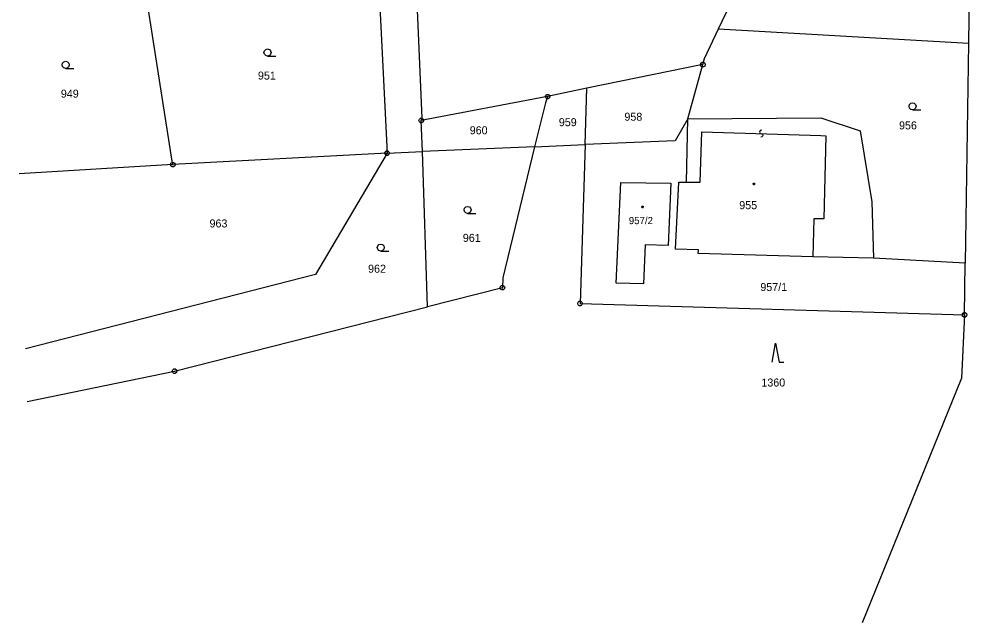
# Model space of a CAD drawing. Extents: x -456675 to -456278, y -1112395 to -1112217.
# Drawn here: x -456664.8 to -456563.6, y -1112392.8 to -1112328.7 of the extents above; entities that cross this region are included whole.
import ezdxf

# ---------------------------------------------------------------- set-up
doc = ezdxf.new("R2010")
doc.units = 0
doc.layers.add('Katastralni_mapa', color=7, linetype='Continuous')

msp = doc.modelspace()

# ---------------------------------------------------------------- linework, layer by layer
at = {"layer": 'Katastralni_mapa'}
for points in [[(-456590.54, -1112329.78), (-456578.75, -1112305.2)], [(-456563.64, -1112304.41), (-456564.02, -1112331.27)], [(-456627.45, -1112308.3), (-456625.73, -1112342.97)], [(-456648.52, -1112343.82), (-456653.24, -1112313.68)], [(-456622.01, -1112339.26), (-456622.84, -1112319.54)], [(-456592.04, -1112332.9), (-456590.54, -1112329.78)], [(-456590.54, -1112329.78), (-456564.02, -1112331.27)], [(-456564.02, -1112331.27), (-456564.35, -1112354.63)], [(-456638.41, -1112332.65), (-456638.6, -1112332.6), (-456638.74, -1112332.46), (-456638.79, -1112332.28), (-456638.74, -1112332.09), (-456638.6, -1112331.95), (-456638.41, -1112331.9), (-456638.22, -1112331.95), (-456638.08, -1112332.09), (-456638.04, -1112332.28), (-456638.08, -1112332.46), (-456638.22, -1112332.6), (-456638.41, -1112332.65), (-456637.54, -1112332.65)], [(-456659.84, -1112333.96), (-456660.03, -1112333.91), (-456660.17, -1112333.77), (-456660.22, -1112333.58), (-456660.17, -1112333.4), (-456660.03, -1112333.26), (-456659.84, -1112333.21), (-456659.65, -1112333.26), (-456659.52, -1112333.4), (-456659.47, -1112333.58), (-456659.52, -1112333.77), (-456659.65, -1112333.91), (-456659.84, -1112333.96), (-456658.97, -1112333.96)], [(-456592.21, -1112333.56), (-456604.53, -1112336.06)], [(-456593.79, -1112339.32), (-456592.21, -1112333.56)], [(-456592.24, -1112333.56), (-456592.19, -1112333.56)], [(-456592.21, -1112333.56), (-456592.04, -1112332.9)], [(-456604.53, -1112336.06), (-456608.68, -1112336.96)], [(-456604.71, -1112342.06), (-456604.53, -1112336.06)], [(-456608.68, -1112336.96), (-456622.09, -1112339.49)], [(-456608.92, -1112337.61), (-456610.06, -1112342.29)], [(-456608.68, -1112336.96), (-456608.92, -1112337.61)], [(-456608.7, -1112336.96), (-456608.66, -1112336.96)], [(-456569.95, -1112338.37), (-456570.14, -1112338.32), (-456570.27, -1112338.18), (-456570.32, -1112337.99), (-456570.27, -1112337.81), (-456570.14, -1112337.67), (-456569.95, -1112337.62), (-456569.76, -1112337.67), (-456569.62, -1112337.81), (-456569.57, -1112337.99), (-456569.62, -1112338.18), (-456569.76, -1112338.32), (-456569.95, -1112338.37), (-456569.07, -1112338.37)], [(-456622.12, -1112339.49), (-456622.07, -1112339.49)], [(-456622.09, -1112339.49), (-456622.01, -1112339.26)], [(-456621.97, -1112342.8), (-456622.09, -1112339.49)], [(-456593.79, -1112339.32), (-456595.14, -1112341.65)], [(-456593.95, -1112346.04), (-456593.79, -1112339.32)], [(-456593.79, -1112339.32), (-456579.69, -1112339.22)], [(-456579.69, -1112339.22), (-456575.5, -1112340.58)], [(-456592.48, -1112346.03), (-456592.32, -1112340.69)], [(-456592.32, -1112340.69), (-456579.68, -1112341.1)], [(-456585.96, -1112340.52), (-456586.11, -1112340.57), (-456586.18, -1112340.72), (-456586.11, -1112340.86), (-456585.88, -1112340.95), (-456585.82, -1112341.09), (-456585.9, -1112341.23), (-456586.04, -1112341.27)], [(-456575.5, -1112340.58), (-456574.25, -1112348.13)], [(-456595.14, -1112341.65), (-456604.71, -1112342.06)], [(-456579.68, -1112341.1), (-456579.15, -1112341.11)], [(-456579.15, -1112341.11), (-456579.37, -1112349.95)], [(-456625.73, -1112342.97), (-456621.97, -1112342.8)], [(-456610.06, -1112342.29), (-456621.97, -1112342.8)], [(-456621.42, -1112359.27), (-456621.97, -1112342.8)], [(-456610.06, -1112342.29), (-456613.45, -1112356.19)], [(-456610.06, -1112342.29), (-456604.71, -1112342.06)], [(-456604.71, -1112342.06), (-456605.24, -1112358.93)], [(-456648.47, -1112344.18), (-456648.52, -1112343.82)], [(-456625.73, -1112342.97), (-456648.47, -1112344.18)], [(-456625.73, -1112342.97), (-456633.33, -1112355.85)], [(-456625.76, -1112342.97), (-456625.7, -1112342.97)], [(-456648.47, -1112344.18), (-456664.79, -1112345.15)], [(-456648.49, -1112344.18), (-456648.44, -1112344.18)], [(-456601.41, -1112356.76), (-456600.92, -1112346.07)], [(-456600.92, -1112346.07), (-456595.59, -1112346.15)], [(-456595.59, -1112346.15), (-456595.87, -1112352.78)], [(-456595.09, -1112353.16), (-456594.77, -1112346.04)], [(-456594.77, -1112346.04), (-456593.95, -1112346.04)], [(-456593.95, -1112346.04), (-456592.48, -1112346.03)], [(-456617.17, -1112349.36), (-456617.36, -1112349.31), (-456617.5, -1112349.17), (-456617.55, -1112348.98), (-456617.5, -1112348.8), (-456617.36, -1112348.66), (-456617.17, -1112348.61), (-456616.98, -1112348.66), (-456616.85, -1112348.8), (-456616.8, -1112348.98), (-456616.85, -1112349.17), (-456616.98, -1112349.31), (-456617.17, -1112349.36), (-456616.3, -1112349.36)], [(-456574.25, -1112348.13), (-456574.1, -1112354.11)], [(-456580.43, -1112349.92), (-456580.52, -1112353.97)], [(-456579.37, -1112349.95), (-456580.43, -1112349.92)], [(-456626.4, -1112353.36), (-456626.59, -1112353.31), (-456626.72, -1112353.17), (-456626.77, -1112352.99), (-456626.72, -1112352.8), (-456626.59, -1112352.66), (-456626.4, -1112352.61), (-456626.21, -1112352.66), (-456626.07, -1112352.8), (-456626.02, -1112352.99), (-456626.07, -1112353.17), (-456626.21, -1112353.31), (-456626.4, -1112353.36), (-456625.52, -1112353.36)], [(-456598.32, -1112352.68), (-456598.5, -1112356.85)], [(-456595.87, -1112352.78), (-456598.32, -1112352.68)], [(-456592.68, -1112353.22), (-456595.09, -1112353.16)], [(-456592.69, -1112353.63), (-456592.68, -1112353.22)], [(-456580.52, -1112353.97), (-456592.69, -1112353.63)], [(-456574.1, -1112354.11), (-456580.52, -1112353.97)], [(-456564.35, -1112354.63), (-456574.1, -1112354.11)], [(-456564.43, -1112360.13), (-456564.35, -1112354.63)], [(-456633.33, -1112355.85), (-456664.12, -1112363.73)], [(-456613.45, -1112356.19), (-456613.48, -1112357.25)], [(-456598.5, -1112356.85), (-456601.41, -1112356.76)], [(-456613.48, -1112357.25), (-456621.42, -1112359.27)], [(-456613.51, -1112357.25), (-456613.45, -1112357.25)], [(-456605.27, -1112358.93), (-456605.21, -1112358.93)], [(-456605.24, -1112358.93), (-456564.43, -1112360.13)], [(-456648.28, -1112366.1), (-456621.42, -1112359.27)], [(-456564.43, -1112360.13), (-456564.75, -1112366.85)], [(-456564.45, -1112360.13), (-456564.41, -1112360.13)], [(-456584.85, -1112365.14), (-456584.48, -1112363.14), (-456584.1, -1112365.14), (-456583.6, -1112365.14)], [(-456663.92, -1112369.34), (-456648.28, -1112366.1)], [(-456648.31, -1112366.1), (-456648.26, -1112366.1)], [(-456564.75, -1112366.85), (-456575.31, -1112392.84)]]:
    msp.add_lwpolyline(points, dxfattribs=at)
for points in [[(-456592.14, -1112333.32), (-456592.01, -1112333.42), (-456591.96, -1112333.56), (-456592.01, -1112333.71), (-456592.14, -1112333.8), (-456592.29, -1112333.8), (-456592.41, -1112333.71), (-456592.46, -1112333.56), (-456592.41, -1112333.42), (-456592.29, -1112333.32)], [(-456608.61, -1112336.72), (-456608.48, -1112336.81), (-456608.43, -1112336.96), (-456608.48, -1112337.1), (-456608.61, -1112337.2), (-456608.76, -1112337.2), (-456608.88, -1112337.1), (-456608.93, -1112336.96), (-456608.88, -1112336.81), (-456608.76, -1112336.72)], [(-456622.02, -1112339.25), (-456621.89, -1112339.34), (-456621.84, -1112339.49), (-456621.89, -1112339.64), (-456622.02, -1112339.73), (-456622.17, -1112339.73), (-456622.29, -1112339.64), (-456622.34, -1112339.49), (-456622.29, -1112339.34), (-456622.17, -1112339.25)], [(-456625.65, -1112342.73), (-456625.53, -1112342.82), (-456625.48, -1112342.97), (-456625.53, -1112343.11), (-456625.65, -1112343.21), (-456625.8, -1112343.21), (-456625.93, -1112343.11), (-456625.98, -1112342.97), (-456625.93, -1112342.82), (-456625.8, -1112342.73)], [(-456648.39, -1112343.94), (-456648.27, -1112344.04), (-456648.22, -1112344.18), (-456648.27, -1112344.32), (-456648.39, -1112344.42), (-456648.55, -1112344.42), (-456648.67, -1112344.32), (-456648.72, -1112344.18), (-456648.67, -1112344.04), (-456648.55, -1112343.94)], [(-456586.79, -1112346.15), (-456586.74, -1112346.16), (-456586.71, -1112346.2), (-456586.7, -1112346.23), (-456586.71, -1112346.28), (-456586.76, -1112346.31), (-456586.79, -1112346.31), (-456586.83, -1112346.3), (-456586.87, -1112346.27), (-456586.88, -1112346.23), (-456586.87, -1112346.19), (-456586.82, -1112346.15)], [(-456598.6, -1112348.59), (-456598.55, -1112348.6), (-456598.53, -1112348.65), (-456598.52, -1112348.68), (-456598.53, -1112348.72), (-456598.57, -1112348.76), (-456598.6, -1112348.76), (-456598.65, -1112348.75), (-456598.68, -1112348.72), (-456598.69, -1112348.68), (-456598.68, -1112348.63), (-456598.64, -1112348.6)], [(-456613.4, -1112357.01), (-456613.28, -1112357.1), (-456613.23, -1112357.25), (-456613.28, -1112357.4), (-456613.4, -1112357.49), (-456613.55, -1112357.49), (-456613.68, -1112357.4), (-456613.73, -1112357.25), (-456613.68, -1112357.1), (-456613.55, -1112357.01)], [(-456605.17, -1112358.69), (-456605.04, -1112358.79), (-456604.99, -1112358.93), (-456605.04, -1112359.07), (-456605.17, -1112359.17), (-456605.32, -1112359.17), (-456605.44, -1112359.07), (-456605.49, -1112358.93), (-456605.44, -1112358.79), (-456605.32, -1112358.69)], [(-456564.36, -1112359.89), (-456564.23, -1112359.98), (-456564.18, -1112360.13), (-456564.23, -1112360.28), (-456564.36, -1112360.37), (-456564.51, -1112360.37), (-456564.63, -1112360.28), (-456564.68, -1112360.13), (-456564.63, -1112359.98), (-456564.51, -1112359.89)], [(-456648.21, -1112365.86), (-456648.08, -1112365.96), (-456648.03, -1112366.1), (-456648.08, -1112366.25), (-456648.21, -1112366.34), (-456648.36, -1112366.34), (-456648.48, -1112366.25), (-456648.53, -1112366.1), (-456648.48, -1112365.96), (-456648.36, -1112365.86)]]:
    msp.add_lwpolyline(points, close=True, dxfattribs=at)

# ---------------------------------------------------------------- texts
for s, height, p in [('951', 0.85, (-456639.43, -1112335.15)), ('949', 0.85, (-456660.35, -1112337.07)), ('958', 0.85, (-456600.53, -1112339.52)), ('959', 0.85, (-456607.49, -1112340.1)), ('956', 0.85, (-456571.38, -1112340.44)), ('960', 0.85, (-456616.95, -1112340.96)), ('955', 0.85, (-456588.34, -1112348.91)), ('957/2', 0.765, (-456600.06, -1112350.5)), ('963', 0.85, (-456644.57, -1112350.85)), ('961', 0.85, (-456617.68, -1112352.38)), ('962', 0.85, (-456627.74, -1112355.66)), ('957/1', 0.85, (-456586.1, -1112357.6)), ('1360', 0.85, (-456585.99, -1112367.74))]:
    msp.add_text(s, height=height, dxfattribs=at).set_placement(p)

doc.saveas('drawing.dxf')
